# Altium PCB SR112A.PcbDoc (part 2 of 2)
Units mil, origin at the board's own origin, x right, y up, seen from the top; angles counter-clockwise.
Board outline 4000 x 3000 mil, 4 copper layers (Top Layer, Signal Layer 1, Signal Layer 2, Bottom Layer), stack 61.2 mil thick; 97 components, 25 nets, 179 pads, 677 vias.
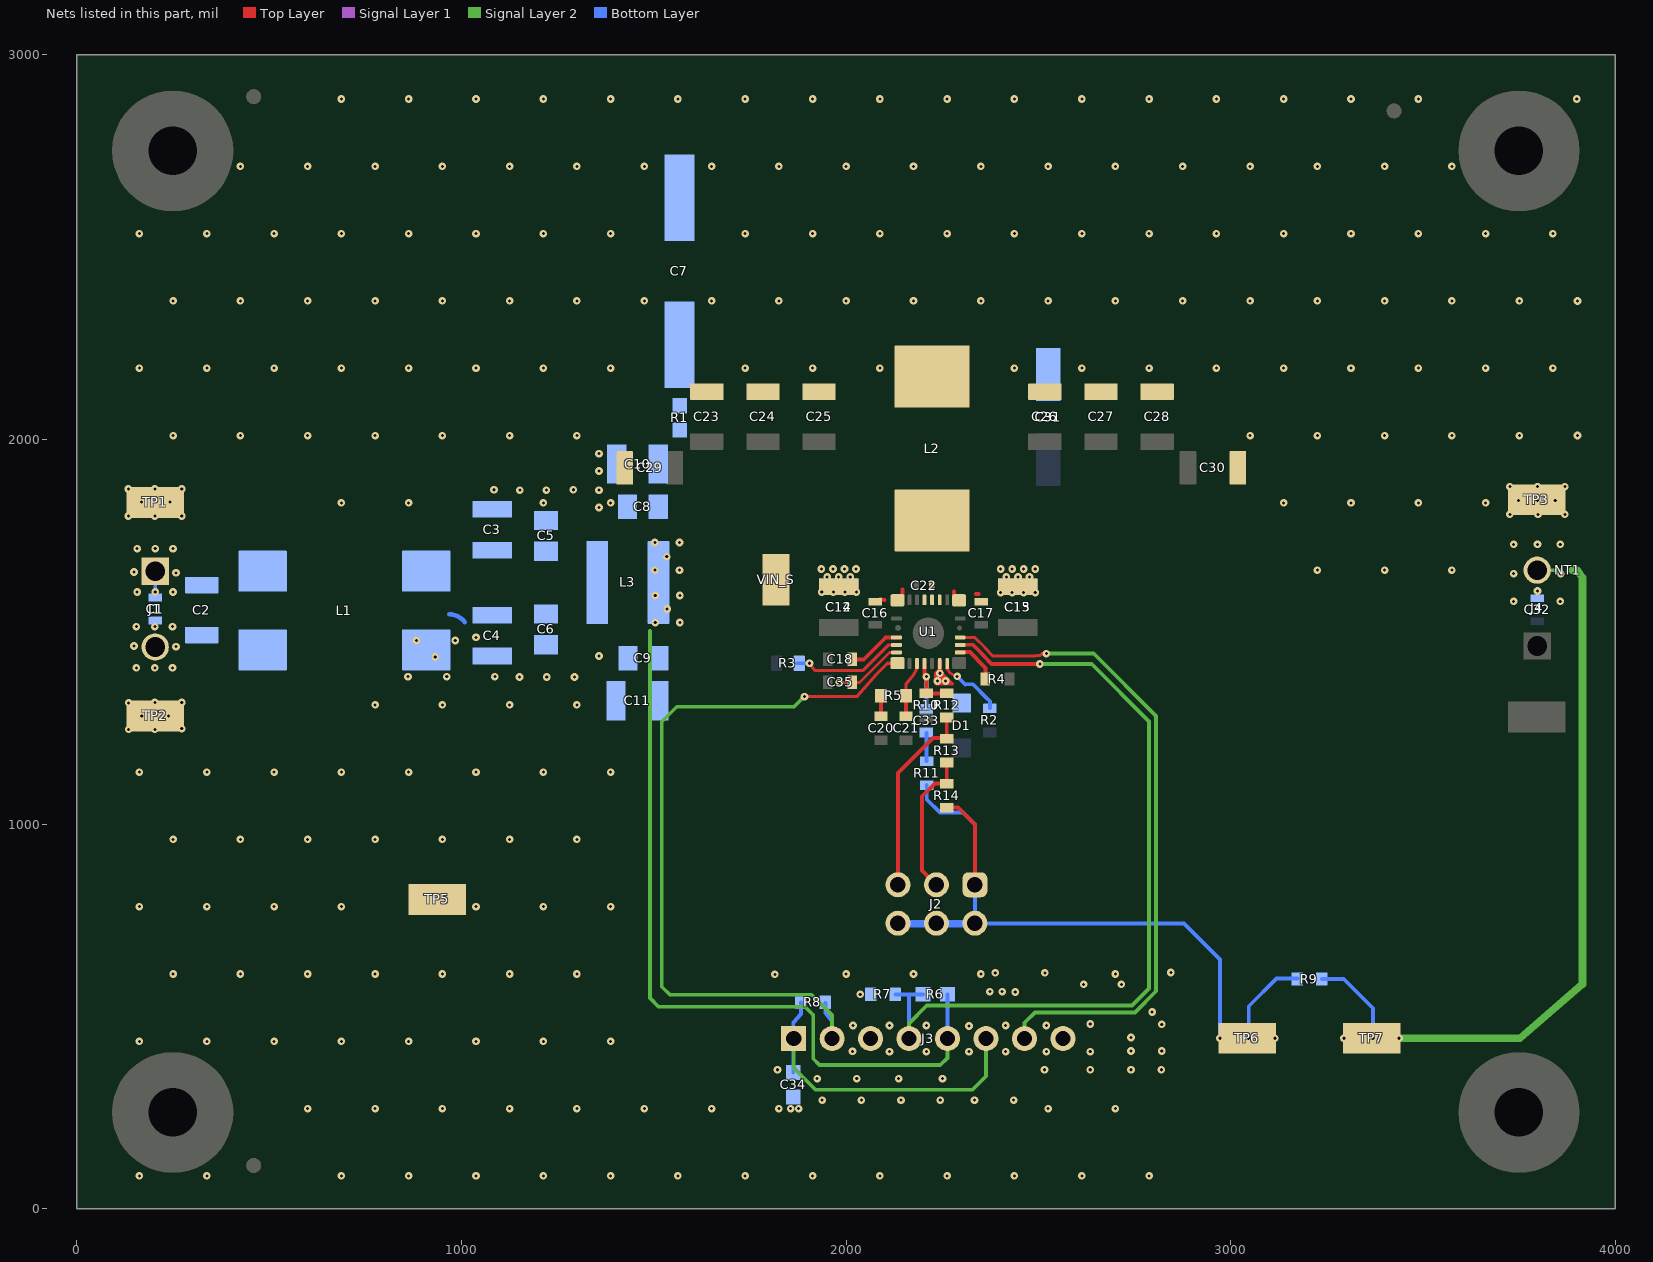
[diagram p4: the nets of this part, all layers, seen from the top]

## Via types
v1: diameter 20, hole 8, Top Layer to Bottom Layer, tented both sides, 441 vias
v2: diameter 19.68, hole 7.87, Top Layer to Bottom Layer, tented both sides, 208 vias
v3: diameter 20, hole 8, Top Layer to Bottom Layer, 28 vias

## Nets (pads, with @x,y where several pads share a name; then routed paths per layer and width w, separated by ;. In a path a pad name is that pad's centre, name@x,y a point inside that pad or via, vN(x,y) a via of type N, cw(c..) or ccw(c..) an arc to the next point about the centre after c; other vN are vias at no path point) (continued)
COMP: C21.2 R5.2 U1.3 | length 145.6
  Top Layer w8: R5.2@2156,1333 2156,1364 2177,1390 U1.3@2185,1405 ; U1.3@2183.38,1405.15 U1.3@2184.47,1417.26
  Top Layer w10: C21.2@2156,1281 R5.2@2156,1333
CONFIG: R2.2 U1.7 | length 180.3
  Top Layer w7: U1.7@2262,1404 2264.22,1400.51
  Top Layer w7.5: U1.7@2263,1417 2265,1401 ; 2265.06,1401.03 2270,1393
  Top Layer w8: 2270,1393 v1@2288,1383
  Bottom Layer w10: v1(2289,1384) 2310,1363 2329.81,1363.19 2365,1328 2374,1319 R2.2@2374,1301
DRSS: R3.2 U1.25 | length 309.8
  Top Layer w8: v1@1905,1413 v1(1905,1418) 1919,1399 ; 1919.31,1398.69 2043.15,1398.69 2109.46,1465 U1.25@2141,1465
  Bottom Layer w10: R3.2@1873,1418 v1(1905,1418)
EN: J3.4 R6.1 R7.2 U1.10 | length 2166.4
  Top Layer w10: U1.10@2288,1466 2330.23,1466 2343.19,1453.04 2378,1416 v1@2503.77,1416
  Signal Layer 2 w10: J3.4@2164,442 2164,481 2210,528 2743.81,528 2788.19,572.38 2788.19,1266.81 2639,1416 v1(2504,1416)
  Bottom Layer w10: R7.2@2128,557 2165,557 R6.1@2200.5,557 ; J3.4@2164,441 2164,556
FB: C33.1 R10.2 R12.2 U1.4 | length 225.1
  Top Layer w10: U1.4@2204,1426 2204,1391 v1(2209,1383) R10.2@2209,1339.5 R12.2@2262,1339.5 2262.5,1339.5 R12.2@2263,1340
  Bottom Layer w10: C33.1@2209,1300 v1(2209,1383)
GND: C3.2 C4.2 C5.2 C6.2 C7.2 C8.2 C9.2 C10.2 C11.2 C23.2 C24.2 C25.2 C26.2 C27.2 C28.2 C29.2 C30.2 C31.1 C32.1 C34.2 C35.1 D1.1 J3.3 J3.8 J4.2 L1.4 L2.2 NT1.1 R7.1 TP3.1 TP5.1 U1.6 U1.26 | length 452.8
  Top Layer w8: v1(1983.31,1368) C35.1@2016.5,1368 2035,1368 2113,1446 U1.26@2140,1446
  Top Layer w10: v1@2249.33,1392.33 2249.33,1390.4 2253.19,1386.55 2253.19,1386.04 2274.04,1365.18 2275.08,1365.18 2275.93,1364.81
  Top Layer w12: v1@2244,1366 v1@2244,1391.34 ; U1.6@2244,1425 2244,1400.34 2235,1391.34 2235,1366 v1@2256,1365.81 ; v1@2245.38,1399.06 v1@2247.91,1391.83 ; 2248,1366 v1@2248,1391.34 ; v1@2252,1366 2273,1365.81
  Signal Layer 2 w10: J4.2@3797,1659.85 3858.04,1659.85 NT1.1@3858.19,1660
  Bottom Layer w10: J4.2@3797,1632 J4.2@3797,1632.15
  other v1: 1856,260 1877,260 1938,282 2040,282 2143,282 2245,282 2334,282 2436,282 1925,338 2028,338 2137,338 2251,338 1822,361 2516,361 2635,361 2741,361 2820,361 2113,408 2209,408 2320,408 2415,408 2521,408 2635,408 2017,409 2741,410 2821,410 2741,445 2320,475 2018,476 2113,476 2209,476 2415,476 2521,476 2821,479 2635,480 2796,511 2037,557 2440,563 2374,564 2406,564 2618,583 2716,583 1815,609 2388,613 2517,613 2844.56,613.83 2238,1372 2259,1372 1151,1382 1222,1382 1294,1382 861,1383 962,1383 1087,1383 2244,1392 932,1434 1358,1437 883,1477 984,1477 3736,1579 3857,1579 3798,1606 3736,1651 3858,1651 3736,1727 3798,1727 3857,1727 3726,1805 3799,1805 3869,1805 1358,1823 3749,1841 3798,1841 3844,1841 1152,1868 1221,1868 1358,1868 1085,1869 1291,1869 3726,1877 3798,1877 3869,1877 1358,1918 1358,1963 3902,2010 3902,2360 3900,2885
  other v2: 163,85 338,85 688,85 863,85 1038,85 1213,85 1388,85 1563,85 1738,85 1913,85 2088,85 2263,85 2438,85 2613,85 2788,85 600.5,260 775.5,260 950.5,260 1125.5,260 1300.5,260 1475.5,260 1650.5,260 1825.5,260 2525.5,260 2700.5,260 163,435 338,435 513,435 688,435 863,435 1038,435 1213,435 1388,435 250.5,610 425.5,610 600.5,610 775.5,610 950.5,610 1125.5,610 1300.5,610 2000.5,610 2175.5,610 2350.5,610 2700.5,610 163,785 338,785 513,785 688,785 1038,785 1213,785 1388,785 250.5,960 425.5,960 600.5,960 775.5,960 950.5,960 1125.5,960 1300.5,960 163,1135 338,1135 513,1135 688,1135 863,1135 1038,1135 1213,1135 1388,1135 775.5,1310 950.5,1310 1125.5,1310 1300.5,1310 1038,1485 3225.5,1660 3400.5,1660 3575.5,1660 688,1835 863,1835 1213,1835 1388,1835 3138,1835 3313,1835 3488,1835 3663,1835 250.5,2010 425.5,2010 600.5,2010 775.5,2010 950.5,2010 1125.5,2010 1300.5,2010 3050.5,2010 3225.5,2010 3400.5,2010 3575.5,2010 3750.5,2010 163,2185 338,2185 513,2185 688,2185 863,2185 1038,2185 1213,2185 1388,2185 1738,2185 1913,2185 2088,2185 2438,2185 2613,2185 2788,2185 2963,2185 3138,2185 3313,2185 3488,2185 3663,2185 3838,2185 250.5,2360 425.5,2360 600.5,2360 775.5,2360 950.5,2360 1125.5,2360 1300.5,2360 1475.5,2360 1650.5,2360 1825.5,2360 2000.5,2360 2175.5,2360 2350.5,2360 2525.5,2360 2700.5,2360 2875.5,2360 3050.5,2360 3225.5,2360 3400.5,2360 3575.5,2360 3750.5,2360 163,2535 338,2535 513,2535 688,2535 863,2535 1038,2535 1213,2535 1388,2535 1738,2535 1913,2535 2088,2535 2263,2535 2438,2535 2613,2535 2788,2535 2963,2535 3138,2535 3313,2535 3488,2535 3663,2535 3838,2535 425.5,2710 600.5,2710 775.5,2710 950.5,2710 1125.5,2710 1300.5,2710 1475.5,2710 1650.5,2710 1825.5,2710 2000.5,2710 2175.5,2710 2350.5,2710 2525.5,2710 2700.5,2710 2875.5,2710 3050.5,2710 3225.5,2710 3400.5,2710 3575.5,2710 688,2885 863,2885 1038,2885 1213,2885 1388,2885 1563,2885 1738,2885 1913,2885 2088,2885 2263,2885 2438,2885 2613,2885 2788,2885 2963,2885 3138,2885 3313,2885 3488,2885
GND_SENSE: NT1.2 R9.2 TP7.1 | length 2083.5
  Signal Layer 2 w20: NT1.2@3888,1660 3901,1660 3915,1640 3915,583.74 3752.08,443 v1(3438,443) v1(3370,443) ; v1(3370,443) v1(3295,443) v1(3370,443)
  Bottom Layer w10: R9.2@3237,597 3294,597 3370,521 v1(3370,443)
INJ: J2.1 J2.2 J2.4 J2.6 R9.1 R11.2 R14.2 TP6.1 | length 2156.5
  Top Layer w10: R14.2@2262,1043 2291,1043 2335,999 J2.1@2335,842
  Signal Layer 1 w10: v1(2972,443) v1(3047,443) v1(3115,443)
  Bottom Layer w10: R11.2@2210,1101 2210,1064 2244,1030 2304,1030 2335,999 J2.1@2335,842 J2.2@2335,742 ; J2.2@2336,741 2879,741 2972,648 v1(2972,443) ; v1(3047,443) 3047,526 3119,598 R9.1@3174,598
  Bottom Layer w20: J2.6@2134,741 J2.4@2235,741 ; J2.4@2236,741 J2.2@2335,741
MODE/SYNC: J3.7 U1.11 | length 1742.1
  Top Layer w8: U1.11@2287,1485 2335,1485 2360,1460 2360,1459.7 2381.33,1437 2494.15,1437 2495.15,1438 2505,1438 2510,1443 v1(2521,1443)
  Signal Layer 2 w10: J3.7@2464,442 2464,483.19 2491,510.19 2751.19,510.19 2806,565 2806,1281 2644,1443 v1(2521,1443)
NetC3_1: C3.1 C4.1 C5.1 C6.1 L1.3 L3.2 | length 47
  Bottom Layer w12: 968.01,1545.33 cw(c967.04,1492.6) 1008.68,1524.97
NetC7_1: C7.1 R1.1
NetC20_1: C20.1 R5.1 | length 53
  Top Layer w10: C20.1@2091,1280 R5.1@2091,1333
NetC33_2: C33.2 R11.1 | length 73
  Bottom Layer w10: R11.1@2209,1164 C33.2@2209,1237
NetC34_1: C34.1 J3.1 J3.6 R8.1 | length 900.8
  Signal Layer 2 w10: J3.1@1864,442 1864,366 1921,309 2329,309 2364,344 J3.6@2364,442
  Bottom Layer w10: C34.1@1863,354 J3.1@1863,444 ; J3.1@1863,445 1863,484 1883,506 R8.1@1883,536
NetJ2_3: J2.3 R13.1 R14.1 | length 378
  Top Layer w10: J2.3@2235,842 2198,879 2198,1072 2231,1105 R14.1@2262,1105 R13.1@2262,1160
NetJ2_5: J2.5 R12.1 R13.2 | length 508.7
  Top Layer w10: J2.5@2135,842 2135,1133 2226,1224 2262,1224 R12.1@2262,1277
PG: J3.2 R8.2 U1.1 | length 1995.2
  Top Layer w8: v1(1892,1331) 2027.98,1331 2080,1390 2108,1418 U1.1@2134,1418
  Signal Layer 2 w10: v1(1892,1331) 1891,1331 1865,1305 1560,1305 1521,1266 1521,577 1542,556 1911,556 1931,536 1964,503 J3.2@1964,442
  Bottom Layer w10: 1946.91,507.93 1963,489 ; 1947,508 R8.2@1947,534.5 ; J3.2@1964,446 1964,488
RT: R4.2 U1.9 | length 118.6
  Top Layer w10: U1.9@2288,1446.8 2322.08,1446.8 2359,1409.88 ; 2360.41,1408.41 2362.5,1406.31 R4.2@2362.5,1377
SW: C22.2 L2.1 U1.16 U1.17 U1.18
VCC: C18.1 U1.24 | length 147.9
  Top Layer w10: C18.1@2016,1428 C18.1@2016.5,1428 2046.26,1428 2103.26,1485 ; 2103,1485 U1.24@2140,1485
VIN: C8.1 C9.1 C10.1 C11.1 C12.1 C13.1 C14.1 C15.1 C16.1 C17.1 J3.5 L3.1 R1.2 R6.2 U1.14 U1.21 VIN_S.1 | length 2121.7
  Top Layer w10: C16.1@2089,1585 2100,1582 ; U1.21@2133.78,1581.63 2147,1594.85 2147,1610 ; 2281,1605 2281,1594.85 U1.14@2294.22,1581.63 ; 2338,1598 2345,1598
  Signal Layer 2 w10: 1490,1502 1490,548 1512,525 1839,525 1893,525 1915,503 1915,389.5 1931.5,373 2245,373 2264,392 J3.5@2264,442
  Bottom Layer w10: J3.5@2263.5,441.5 R6.2@2263.5,557
  other v1: 1504,1524 1568,1524 1535,1559 1504,1594 1568,1594 2402,1602 2432,1602 2462,1602 2492,1602 1937,1603 1967,1603 1997,1603 2027,1603 1951,1642 1981,1642 2011,1642 2417,1642 2447,1642 2477,1642 1503,1660 1567,1660 1936,1663 1966,1663 1996,1663 2026,1663 2402,1663 2432,1663 2462,1663 2492,1663 1534,1695 1503,1732 1567,1732
VIN+: C1.1 C2.1 J1.1 L1.2 TP1.1 | length 55.4
  Top Layer w10: TP1.1@203,1836 TP1.1@204,1835
  Bottom Layer w10: v3(204,1603) J1.1@204,1656.85 J1.1@204,1657
  other v1: 203,1801 168,1837 242,1837 203,1871
  other v3: 157,1603 250,1603 258,1653 149,1655 157,1716 204,1716 250,1716 134,1801 273,1801 134,1871 273,1871
VIN-: C1.2 C2.2 J1.2 L1.1 TP2.1
  other v3: 135,1246 203,1246 273,1248 169,1281 238,1281 135,1315 203,1316 273,1316 155,1406 203,1406 249,1406 258,1461 149,1463 155,1513 203,1513 249,1513
pads on no net: FID1.1 FID2.1 FID3.1 FID4.1 FID5.1 FID6.1 H1.1 H2.1 H3.1 H4.1 H5.0 H6.0 H7.0 H8.0 LBL1.0 SH-J1.0 SH-J2.0 SH-J3.0 U1.2 U1.5 U1.15 U1.20

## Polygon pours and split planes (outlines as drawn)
GND_SENSE on Top Layer "TOP_LAYER_GND_SENSE_P2690" (solid, remove dead copper, pour order 2690): 3279.64,495 3453.65,495 3453.65,391 3279.64,391
INJ on Top Layer "TOP_LAYER_INJ_P2691" (solid, remove dead copper, pour order 2691): 2955.64,494.76 3129.64,494.76 3129.64,390.76 2955.64,390.76
VIN on Top Layer "TOP_LAYER_VIN_P2692" (solid, remove dead copper, pour order 2692): 2276,1566 2527,1566 2527,1706 2344,1706 2276,1636
VIN on Top Layer "TOP_LAYER_VIN_P2693" (solid, remove dead copper, pour order 2693): 2152,1566 1781,1566 1781,1706 2103.61,1706 2152,1657.61
GND on Top Layer "TOP_LAYER_GND_P2694" (solid, remove dead copper, pour order 2694): 3709,1899.53 3709,1558 3884,1558 3884,1900.51
VIN- on Top Layer "TOP_LAYER_VIN-_P2695" (solid, remove dead copper, pour order 2695): 109,1222 109,1545 299,1545 299,1222
VIN+ on Top Layer "TOP_LAYER_VIN+_P2696" (solid, remove dead copper, pour order 2696): 109,1896 109,1571 299,1571 299,1896
GND on Top Layer "TOP_LAYER_GND_P2697" (solid, remove dead copper, pour order 2697): 849.77,1360.44 606.77,1360.44 394.19,1154 849.77,1154
GND on Top Layer "TOP_LAYER_GND_P2698" (solid, remove dead copper, pour order 2698): 1485.15,2066.88 1485.15,1552.88 24.15,1552.88 24.15,2066.88
GND on Top Layer "TOP_LAYER_GND_P2699" (solid, remove dead copper, pour order 2699): 1779,2975 1779,2064 25,2064 25,2975
GND on Top Layer "TOP_LAYER_GND_P2700" (solid, remove dead copper, pour order 2700): 1485,1159 1485,634.39 2003.85,634.39 2858,634.39 2858,25 33.24,25 26,32.24 26,1159
GND on Top Layer "TOP_LAYER_GND_P2701" (solid, remove dead copper, pour order 2701): 1773,2975 1773,2064 2951,2064 2951,1920 3324,1547 3975,1547 3975,2975
-VOUT on Top Layer "TOP_LAYER_-VOUT_P2702" (solid, remove dead copper, pour order 2702): 1495,2054 2949,2054 2949,1908 3320,1537 3975,1537 3975,25 2869,25 2869,640 2870,641 1495,641
GND on Signal Layer 2 "SIGNAL_LAYER_2_GND_P2720" (solid, remove dead copper, pour order 2720): 25,2975 26,2974 26,25 3975,25 3975,2975
INJ on Signal Layer 2 "SIGNAL_LAYER_2_INJ_P2713" (solid, remove dead copper, pour order 2713): 2955.98,494.96 3129.98,494.96 3129.98,390.96 2955.98,390.96
GND_SENSE on Signal Layer 2 "SIGNAL_LAYER_2_GND_SENSE_P2712" (solid, remove dead copper, pour order 2712): 3280,495 3454,495 3454,391 3280,391
GND on Signal Layer 2 "SIGNAL_LAYER_2_GND_P2714" (solid, remove dead copper, pour order 2714): 850,1361 607,1361 351.63,1113 850,1113
VIN on Signal Layer 2 "SIGNAL_LAYER_2_VIN_P2715" (solid, remove dead copper, pour order 2715): 1485.26,1770.9 1485.36,1771 1805,1770.9 2526,1770.9 2526,1589 1901,1589 1805,1493 1485,1493 1485,1771
GND on Signal Layer 2 "SIGNAL_LAYER_2_GND_P2716" (solid, remove dead copper, pour order 2716): 1836.42,2067 1448.03,1553 24,1553 24,2067
GND on Signal Layer 2 "SIGNAL_LAYER_2_GND_P2717" (solid, remove dead copper, pour order 2717): 1778.5,2974 1778.5,2047.79 25.5,2047.79 25.5,2974
GND on Signal Layer 2 "SIGNAL_LAYER_2_GND_P2718" (solid, remove dead copper, pour order 2718): 3975,2974 3975,1553 3098.51,1553 2228.68,2430.92 2228.68,2974
GND on Signal Layer 2 "SIGNAL_LAYER_2_GND_P2719" (solid, remove dead copper, pour order 2719): 1466,1149 1466,631 2004,631 2856,631 2856,27 28,27 27,28 27,1149
INJ on Bottom Layer "BOTTOM_LAYER_INJ_P2726" (solid, remove dead copper, pour order 2726): 2955.64,494.76 3129.64,494.76 3129.64,390.76 2955.64,390.76
GND_SENSE on Bottom Layer "BOTTOM_LAYER_GND_SENSE_P2725" (solid, remove dead copper, pour order 2725): 3280,495 3454,495 3454,391 3280,391
GND on Bottom Layer "BOTTOM_LAYER_GND_P2722" (solid, remove dead copper, pour order 2722): 2226,1402 2226,1362.91 2260.5,1288 2326,1288 2326,1338 2262,1402
GND on Bottom Layer "BOTTOM_LAYER_GND_P2736" (solid, remove dead copper, pour order 2736): 1730,2975 1730,2063.93 2951,2063.93 2951,1919 3323,1547 3975,1547 3975,2975
-VOUT on Bottom Layer "BOTTOM_LAYER_-VOUT_P2737" (solid, remove dead copper, pour order 2737): 1469.04,2054 2949,2054 2949,1907 3319,1537 3975,1537 3975,25 3966.67,25 2843.04,25 2843.04,644 1469.04,644
GND on Bottom Layer "BOTTOM_LAYER_GND_P2721" (solid, remove dead copper, pour order 2721): 3779,1584 3815,1584 3815,1685 3779,1685
VIN on Bottom Layer "BOTTOM_LAYER_VIN_P2723" (solid, remove dead copper, pour order 2723): 1925,1592 1925,1674 2039,1674 2039,1592
VIN on Bottom Layer "BOTTOM_LAYER_VIN_P2724" (solid, remove dead copper, pour order 2724): 2389,1591 2389,1675 2504,1675 2504,1591
NetC7_1 on Bottom Layer "BOTTOM_LAYER_NETC7_1_P2727" (solid, remove dead copper, pour order 2727): 1527,2360 1527,2066 1609,2066 1609,2360
GND on Bottom Layer "BOTTOM_LAYER_GND_P2728" (solid, remove dead copper, pour order 2728): 850,1360 607,1360 389.73,1149 850,1149
NetC3_1 on Bottom Layer "BOTTOM_LAYER_NETC3_1_P2729" (solid, remove dead copper, pour order 2729): 837,1736 1381,1736 1381,1519 837,1519
VIN- on Bottom Layer "BOTTOM_LAYER_VIN-_P2730" (solid, remove dead copper, pour order 2730): 103,1545 553,1545 553,1386.28 375.3,1218 103,1218
VIN+ on Bottom Layer "BOTTOM_LAYER_VIN+_P2731" (solid, remove dead copper, pour order 2731): 103,1565 103,1900 376,1900 553,1723 553,1565
VIN on Bottom Layer "BOTTOM_LAYER_VIN_P2732" (solid, remove dead copper, pour order 2732): 1483,1169 1483,2048 1650,2048 1650,1169
GND on Bottom Layer "BOTTOM_LAYER_GND_P2733" (solid, remove dead copper, pour order 2733): 1652.41,2072 1446.74,1551.9 22.71,1551.9 22.71,2072
GND on Bottom Layer "BOTTOM_LAYER_GND_P2734" (solid, remove dead copper, pour order 2734): 1778.99,2975 1778.99,2065 25,2065 25,2975
GND on Bottom Layer "BOTTOM_LAYER_GND_P2735" (solid, remove dead copper, pour order 2735): 1463,1152 1463,634 2006,634 2858,634 2858,25 35,25 26,34 26,1152 1449,1152
INJ on Signal Layer 1 "SIGNAL_LAYER_1_INJ_P2705" (solid, remove dead copper, pour order 2705): 2955.98,494.96 3129.98,494.96 3129.98,390.96 2955.98,390.96
GND_SENSE on Signal Layer 1 "SIGNAL_LAYER_1_GND_SENSE_P2704" (solid, remove dead copper, pour order 2704): 3280,495 3454,495 3454,391 3280,391
GND on Signal Layer 1 "SIGNAL_LAYER_1_GND_P2710" (solid, remove dead copper, pour order 2710): 1726,2975 1726,2063.56 2950.95,2063.56 2950.95,1920.05 3324,1547 3975,1547 3975,2975
-VOUT on Signal Layer 1 "SIGNAL_LAYER_1_-VOUT_P2711" (solid, remove dead copper, pour order 2711): 1495,2054 2949,2054 2949,1908 3320,1537 3975,1537 3975,25 2869,25 2869,640 2870,641 1495,641
GND on Signal Layer 1 "SIGNAL_LAYER_1_GND_P2706" (solid, remove dead copper, pour order 2706): 849.08,1361.13 606.08,1361.13 374.26,1136 849.08,1136
GND on Signal Layer 1 "SIGNAL_LAYER_1_GND_P2707" (solid, remove dead copper, pour order 2707): 1485,2067 1485,1553 24,1553 24,2067
GND on Signal Layer 1 "SIGNAL_LAYER_1_GND_P2708" (solid, remove dead copper, pour order 2708): 1778.5,2975 1778.5,2064 25.5,2064 25.5,2975
GND on Signal Layer 1 "SIGNAL_LAYER_1_GND_P2709" (solid, remove dead copper, pour order 2709): 1485,1155.96 1485.5,631.35 2006.25,631.35 2858.25,631.35 2858.25,25 32.6,25 26,31.6 26,1155.96

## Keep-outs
Keep-Out Layer:
  text ".Layer_Name" at 577,-858.49 h60

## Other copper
Top Layer:
  rectangle net GND: 1379,1366 1485,1486
  rectangle net GND: 842.26,1147 1485,1385
  rectangle net GND: 840,1370 1381,1556
  region net GND: 3884,1900 3707,1900 3707,1791 3884,1791
  pour cut-out: 2160,1563 2160,1549 2268,1549 2268,1563
  pour cut-out: 100,1958 100,1906 309.5,1906 309.5,1958
  pour cut-out: 608.04,1359.71 402.04,1159.71 402.04,1209.81 560.05,1359.71
  pour cut-out: 403.26,1957.39 403.26,1907.84 561.26,1749.84 609.66,1749.84
  pour cut-out: 2075,2063.72 2075,1871 2373,1871 2373,2063.72
  pour cut-out: 2075,1871 2075,1716 2124,1716 2124,1871
  pour cut-out: 2159,1437 2159,1431 2265,1431 2265,1437
  pour cut-out: 1381,1767 1381,1489 1485,1489 1485,1767
  pour cut-out: 553,1750 553,1360 839,1360 839,1750
  pour cut-out: 99.5,1211 99.5,1159 309,1159 309,1211
  pour cut-out: 309.5,1958 309.5,1159 584,1159 584,1958
  pour cut-out: 26,1958 26,1159 100,1159 100,1958
  region net SW: 2198,1569 2250,1569 2250,1635 2324,1709 2324,1871 2124,1871 2124,1709 2198,1635
  pour cut-out: 2323,1871 2323,1713 2373,1713 2373,1871
  text ".Layer_Name" at 577,-858.49 h60
Signal Layer 1:
  rectangle net GND: 841.57,1150 1485,1433
  rectangle net GND: 1374,1370 1485,1490
  rectangle net GND: 840,1371 1381,1557
  pour cut-out: 608.43,1359.71 402.43,1159.71 402.43,1209.81 560.44,1359.71
  pour cut-out: 402.96,1957.55 402.96,1908 560.96,1750 609.36,1750
  pour cut-out: 1381,1767 1381,1489 1485,1489 1485,1767
  pour cut-out: 26,1958 26,1159 583,1159 583,1958
  pour cut-out: 553,1750 553,1360 839,1360 839,1750
Signal Layer 2:
  rectangle net GND: 1374,1117 1465,1490
  rectangle net GND: 842.94,1143 1381,1498.23
  rectangle net GND: 839,1370 1381,1556
  pour cut-out: 607.66,1359.71 401.66,1159.71 401.66,1209.81 559.67,1359.71
  pour cut-out: 402.96,1957.55 402.96,1908 560.96,1750 609.36,1750
  pour cut-out: 553,1750 553,1360 839,1360 839,1750
  pour cut-out: 1381,1767 1381,1489 1485,1489 1485,1767
  pour cut-out: 26,1958 26,1159 584,1159 584,1958
Bottom Layer:
  rectangle net GND: 1365,1138 1463,1489
  rectangle net GND: 843.35,1145 1380,1498
  rectangle net NetC3_1: 845,1607 971,1715
  rectangle net VIN+: 421,1608 546,1714
  pour cut-out: 609,1360 403,1160 403,1210.1 561.01,1360
  pour cut-out: 403,1957.55 403,1908 561,1750 609.4,1750
  pour cut-out: 99.25,1212 99.25,1159 402,1159 402,1212
  pour cut-out: 100.03,1958.21 100.03,1905.21 403,1905.21 403,1958.21
  pour cut-out: 25.93,1958.06 25.93,1157.06 99.93,1157.06 99.93,1958.06
  pour cut-out: 1381,1767 1381,1489 1485,1489 1485,1767
  pour cut-out: 553,1750 553,1360 839,1360 839,1750
  pour cut-out: 844,1539.5 844,1509 1002,1509 1002,1539.5
  pour cut-out: 78,1587 78,1531 84.5,1531 84.5,1587
  text ".Layer_Name" at 577,-858.49 h60

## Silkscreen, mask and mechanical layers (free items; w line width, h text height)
Top Overlay:
  text "LM67680-Q1 IBB Converter EVM" at 1009,2839 h150
  text "SR112A" at 516.06,2765.68 h72.83
  text "VIN [3.8V to (65V-|VOUT|)]" at 34.3,2026.88 h100
  text "GND" at 3743,1928 h40
  text "VIN+" at 144.69,1923.68 h72.83
  text "-VOUT" at 3703,1153 h40
  text "VIN-" at 147.97,1138.68 h72.83
  text "VOUT -3.3V to -12V" at 3148.31,1053.99 h100
  text "IOUT up to 6A" at 3220.15,952.32 h100
  text "-VOUT" at 2403,780 h40
  text "Select" at 2404,721 h40
  text "GND" at 882,682 h45
  text "-3.3V" at 2052,656 h25
  text "-12V" at 2293,656 h25
  text "-5V" at 2197,655 h25
  text "GND_SENSE" at 3183,327 h45
  text "INJ" at 2990,323 h45
  text "PG" at 1943,290 h45 r45
  text "EN" at 2144,289 h45 r45
  text "VIN" at 2217,263 h45 r45
  text "GND" at 2513,258 h45 r45
  text "GND" at 2012,257 h45 r45
  text "EXT_PU" at 1715,162 h45 r45
  text "EXT_PU" at 2217,162 h45 r45
  text "MODE/SYNC" at 2224,66 h45 r45
  text ".Layer_Name" at 577,-858.49 h60
Bottom Overlay:
  text ".Layer_Name" at 577,-858.49 h60
Top Paste:
  text ".Layer_Name" at 577,-858.49 h60
Bottom Paste:
  text ".Layer_Name" at 577,-858.49 h60
Top Solder:
  rectangle: 123,1234 285,1328
  rectangle: 122,1789 286,1883
  text ".Layer_Name" at 577,-858.49 h60
  text ".Layer_Name" at 577,-858.49 h60
Bottom Solder:
  text ".Layer_Name" at 577,-858.49 h60
Drill Guide:
  text ".Layer_Name" at 577,-858.49 h60
M1 Board Outline:
  the board outline again, w10
  text ".Layer_Name" at 577,-858.49 h60
M2 Board Dimensions:
  rectangle: 125,-400 500,-275
  rectangle: 0,-275 125,-150
  lines w7: 0,-275 1000,-275 ; 125,-400 125,-150 ; 250,-400 250,-150 ; 500,-400 500,-150 ; 750,-400 750,-150 ; 0,-400 0,-150 1000,-150 1000,-400 0,-400
  text ".Layer_Name" at 577,-858.49 h60
M3 3D STEP Top:
  text ".Layer_Name" at 577,-858.49 h60
M4 3D STEP Bottom:
  text ".Layer_Name" at 577,-858.49 h60
M5 Assembly Top:
  lines w10: -292,-930.17 6308,-930.17 ; -292,-726.83 6310,-726.83 ; -292,-523.5 -292,-1133.5 3713,-1133.5 6310,-1133.5 6310,-523.5 -291.5,-523.5 -291.5,-1133.5 1284,-1133.5 ; 2173,-1133.5 2173,-523.5 ; 3440,-726.83 3440,-523.5 ; 4280,-726.83 4280,-523.5 ; 4902,-1140 4902,-937.17
  text "COMPONENTS MARKED 'DNP' SHOULD NOT BE POPULATED." at 1153.5,-318.5 h60
  text "ASSEMBLY VARIANT:" at 1153,-434 h60
  text ".VariantName" at 2189,-434 h60
  text "PCB VIEWED FROM TOP SIDE" at -228.5,-655.67 h60
  text "BOARD #:" at 2248,-655.67 h60
  text ".PRJ_Number" at 2793.5,-655.67 h60
  text "REV:" at 3638,-655.67 h60
  text ".PCB_Rev" at 3929.5,-655.67 h60
  text "SVN REV:" at 4476,-655.67 h60
  text ".VersionControl_RevNumber" at 4982,-655.67 h60
  text "TID #:" at 2248,-859 h60
  text ".TID" at 2793.5,-859 h60
  text "PLOT NAME =" at -228.5,-1064.34 h60
  text ".plot_File_Name" at 577,-1064.34 h60
  text "GENERATED    :" at 2250,-1064.34 h60
  text ".Print_Date" at 3119.5,-1064.34 h60
  text ".Print_Time" at 3848.5,-1064.34 h60
  text "TEXAS INSTRUMENTS" at 5113,-1064.34 h60
M6 Assembly Bottom:
  lines w10: -292.5,-727.33 6309.5,-727.33 ; -290.5,-930.67 6309.5,-930.67 ; 1115.5,-1140.5 1115.5,-937.67 ; 1737.5,-727.33 1737.5,-524 ; 2577.5,-727.33 2577.5,-524 ; 3844.5,-1134 3844.5,-524 ; 4733.5,-1134 6309,-1134 6309,-524 -292.5,-524 -292.5,-1134 2304.5,-1134 6309.5,-1134 6309.5,-524
  text "COMPONENTS MARKED 'DNP' SHOULD NOT BE POPULATED." at 6102,-318 h60
  text ".VariantName" at 5058,-434 h60
  text "ASSEMBLY VARIANT:" at 6097,-434 h60
  text ".VersionControl_RevNumber" at 1035.5,-656.17 h60
  text "SVN REV:" at 1541.5,-656.17 h60
  text ".PCB_Rev" at 2088,-656.17 h60
  text "REV:" at 2379.5,-656.17 h60
  text ".PRJ_Number" at 3224,-656.17 h60
  text "BOARD #:" at 3769.5,-656.17 h60
  text "PCB VIEWED FROM BOTTOM SIDE" at 6246,-656.17 h60
  text ".TID" at 3224,-859.5 h60
  text "TID #:" at 3769.5,-859.5 h60
  text "TEXAS INSTRUMENTS" at 904.5,-1064.84 h60
  text ".Print_Time" at 2169,-1064.84 h60
  text ".Print_Date" at 2898,-1064.84 h60
  text "GENERATED    :" at 3767.5,-1064.84 h60
  text ".plot_File_Name" at 5440.5,-1064.84 h60
  text "PLOT NAME =" at 6246,-1064.84 h60
M9 Title Sheet:
  drawing of 57 lines, arcs and shapes, not listed
  text "1" at 739.84,8036.5 h70
  text "2" at 3235.5,8036.5 h70
  text "3" at 5724.84,8036.5 h70
  text "4" at 8231.51,8036.5 h70
  text "5" at 10730.5,8036.5 h70
  text "6" at 13235.5,8036.5 h70
  text "A" at -416.5,6893.5 h70
  text "B" at -416.5,4513.5 h70
  text "B" at 14383.5,4513.5 h70
  text "C" at -416.5,2138.5 h70
  text "C" at 14383.5,2138.5 h70
  text "PROJECT TITLE:" at 11343.5,277.5 h45
  text ".PRJ_Title" at 11393.5,144.17 h70
  text "DESIGNED FOR:" at 11343.5,-23.5 h45
  text ".PRJ_Customer" at 11393.5,-163.5 h70
  text "D" at -416.5,-231.5 h70
  text "D" at 14383.5,-231.5 h70
  text "FILE NAME:" at 11343.5,-323.5 h45
  text ".PCB_File_Name_No_Path" at 11393.5,-443.5 h70
  text "Texas Instruments (TI) and/or its licensors do not warrant the accuracy or completeness of this specification" at 6374,-605.34 h45
  text "ENGINEER:" at 11343.5,-613.5 h45
  text "LAYOUT BY:" at 12848.5,-613.5 h45
  text "or any information contained therein. TI and/or its licensors do not warrant that this design will meet" at 6329.01,-718 h45
  text ".PRJ_Engineer" at 11393.5,-768.49 h70
  text ".PCB_Layout" at 12899,-768.49 h70
  text "the specifications, will be suitable for your application or fit for any particular purpose, or will operate in" at 6329.01,-830.67 h45
  text ".Layer_Name" at 577,-858.49 h60
  text "ALTIUM DESIGNER VERSION:" at 12848.5,-923.5 h45
  text "an implementation. TI and/or its licensors do not warrant that the design is production worthy. You should" at 6329.01,-943.33 h45
  text "completely validate and test your design implementation to confirm the system functionality for your application." at 6374,-1056 h45
  text ".print_Scale" at 11393.5,-1056.83 h70
  text ".Application_BuildNumber" at 12899,-1056.83 h70
  text "1" at 739.84,-1263.5 h70
  text "2" at 3235.5,-1263.5 h70
  text "3" at 5724.84,-1263.5 h70
  text "4" at 8231.51,-1263.5 h70
  text "5" at 10730.5,-1263.5 h70
  text "6" at 13235.5,-1263.5 h70
M10 Fab Notes:
  drawing of 189 lines, arcs and shapes, not listed
  text "DESIGN INFORMATION" at 12382.02,6356.17 h60
  text "MIN. TRACK WIDTH:" at 11737.46,6224.05 h60
  text "8" at 12833.7,6224.05 h60
  text "MIL" at 12988.46,6224.05 h60
  text "MIN. CLEARANCE:" at 11737.46,6099.92 h60
  text "0.2" at 12773.7,6099.93 h60
  text "mm" at 12988.46,6099.92 h60
  text "MIN. VIA PAD SIZE:" at 11737.46,5975.8 h60
  text "20" at 12803.71,5975.8 h60
  text "MIL" at 12988.46,5975.8 h60
  text "0.05mm (2MIL)" at 12432.46,5845.9 h60
  text "MINIMUM ANNULAR RING" at 11408.23,5837.67 h60
  text "EXTERNAL" at 13140.46,5837.67 h60
  text "PER" at 11608.23,5727.55 h60
  text "IPC-D-275 CLASS 2 LEVEL C" at 11828.23,5727.54 h60
  text "MIL, HOLES" at 13316.46,5627.07 h60
  text "+/-" at 12924,5618.48 h60
  text "+/-" at 13778,5618.48 h60
  text "REGISTRATION TOLERANCES:" at 11408.23,5617.42 h60
  text "METAL" at 12608,5617.42 h60
  text "5" at 13184.2,5617.42 h60
  text "3" at 14017.2,5617.42 h60
  text "MIL" at 14133.46,5617.42 h60
  text "HOLE SIZE TOLERANCE (UNLESS OTHERWISE SPECIFIED):" at 11408.23,5519.1 h60
  text "+/-" at 13778,5516.23 h60
  text "3" at 14017.2,5515.17 h60
  text "MIL" at 14133.46,5515.17 h60
  text "MATERIAL:" at 11333.46,5377.52 h60
  text "FR-4 High Tg" at 12319.9,5249 h60
  text "X" at 12175.46,5241.01 h60
  text "FR-408" at 11754.46,5236.49 h60
  text "OTHER" at 13242.46,5236.49 h60
  text "62 MIL (1.6mm) +/-10%" at 12074.56,5093.46 h60
  text "X" at 11954.46,5091.01 h60
  text "THICKNESS:" at 11408.23,5085.24 h60
  text "OTHER" at 13359.46,5085.24 h60
  text "TOLERANCE:" at 11408.23,4946.92 h60
  text "X" at 12256.46,4946.92 h60
  text "ANSI IPC-6012 TYPE 3 CLASS 2" at 12434.48,4946.92 h60
  text "OTHER +/-" at 12434.46,4802.73 h60
  text "BOW & TWIST:" at 11408.23,4657.54 h60
  text "X" at 12256.46,4657.54 h60
  text "ANSI IPC-6012 TYPE 3 CLASS 2" at 12434.48,4657.54 h60
  text "OTHER +/-" at 12434.46,4510.85 h60
  text "DRILLING:" at 11333.46,4380.23 h60
  text "NC_DRILL FILES" at 13094.46,4275.04 h60
  text "REFERENCE:" at 11408.23,4271.1 h60
  text "X" at 12065.46,4271.01 h60
  text "AS SHOWN" at 12243.46,4271.1 h60
  text "X" at 12966.46,4271.1 h60
  text "OTHER" at 13392.46,4128.85 h60
  text "PTH COPPER THICKNESS:" at 11407.91,4125.32 h60
  text "X" at 12547.14,4125.32 h60
  text "20-30 um" at 12675.14,4125.32 h60
  text "BOARD FINISH:" at 11333.46,3977.73 h60
  text "SILKSCREEN:" at 11488.68,3867.6 h60
  text "X" at 12446.46,3867.6 h60
  text "TOP" at 12563.46,3867.6 h60
  text "X" at 12956.46,3867.6 h60
  text "BOTTOM" at 13074.46,3867.6 h60
  text "SILKSCREEN COLOR:" at 11488.68,3712.41 h60
  text "X" at 12445.46,3712.41 h60
  text "WHITE" at 12563.46,3712.41 h60
  text "OTHER" at 13074.46,3712.41 h60
  text "X" at 12576.46,3568.96 h60
  text "GREEN" at 12694.46,3568.96 h60
  text "OTHER" at 13312.46,3568.96 h60
  text "SOLDER RESIST COLOR:" at 11488.68,3562.1 h60
  text "X" at 12576.46,3414.71 h60
  text "MATTE" at 12694.46,3414.71 h60
  text "SEMI-GLOSS" at 13312,3414.07 h60
  text "IMMERSION GOLD (ENIG)" at 12394.46,3241.94 h60
  text "ENEPIG" at 13732,3234.72 h60
  text "SURFACE FINISH:" at 11333.46,3233.72 h60
  text "X" at 12216.46,3233.72 h60
  text "IMM. TIN/SILVER OR EQUIV" at 11663,3096.4 h60
  text "OTHER" at 13094.46,3092.47 h60
  text "ARRAY/PANEL:" at 11333.46,2937.09 h60
  text "CUT AND TRIM PER M1 BOARD OUTLINE" at 12394.46,2928.87 h60
  text "N.C. ROUTE" at 12394.46,2792.9 h60
  text "X" at 13082.46,2792.9 h60
  text "V. SCORE" at 13260.46,2792.9 h60
  text "CERTIFICATION:" at 11333.46,2663.77 h60
  text "MATERIALS AND WORKMANSHIP FOR ALL PCBS" at 12058.46,2663.77 h60
  text "TO MEET OR EXCEED THE REQUIREMENTS OF:" at 12058.46,2569.71 h60
  text "X" at 11695.97,2441.08 h60
  text "ANSI IPC-A-600F CLASS ->" at 11823.96,2441.08 h60
  text "X" at 13471.97,2441.08 h60
  text "2" at 13581.96,2441.08 h60
  text "1" at 13266.96,2439.58 h60
  text "3" at 13935.96,2439.58 h60
  text "X" at 12507.97,2293.39 h60
  text "RoHS" at 12635.96,2293.39 h60
  text "OTHER" at 13280.36,2293.39 h60
  text "PER ORDER" at 13677.42,2293.39 h60
  text "ALL BOARDS MUST MEET OR EXCEED UL94-V0 REQUIREMENTS." at 11361,2139.57 h60
  text "PCB MUST BEAR THE UL94V-0 UL REGISTERED MATERIAL ID NUMBER" at 11361,2023.5 h60
  text "ADDITIONAL REQUIREMENTS:" at 11333.46,1854.08 h60
  text "MICROSECTION:" at 11408.23,1746.95 h60
  text "YES" at 12313.96,1746.95 h60
  text "REQUIRED" at 13175.46,1602.62 h60
  text "BARE BOARD ELEC. TEST:" at 11408.23,1599.76 h60
  text "NONE" at 12713.96,1599.76 h60
  text "X" at 13057.46,1599.76 h60
  text "PER ORDER" at 13767.46,1599.76 h60
  text "XX MIL VIAS REQUIRE NON-CONDUCTIVE FILL AND PLANARIZE" at 11576.38,1394.82 h59
  text "XX MIL VIAS REQUIRE CONDUCTIVE FILL AND PLANARIZE" at 11584.38,1290.84 h60
  text "OUTER XX MIL TRACES REQUIRE 50 OHM SINGLE-ENDED IMPEDANCE" at 11583.39,1127.46 h58
  text "LAYER 2 & 3 (INNER LAYERS) XX MIL WIDE, XX MIL SPACE / TRACES REQUIRE 100 OHM DIFFERENTIAL IMPEDANCE" at 11575.39,891.74 h60
  text ".Layer_Name" at 577,-858.49 h60
M11 Gerber Information:
  lines w10: -292,-930.17 6308,-930.17 ; -292,-726.83 6310,-726.83 ; -292,-523.5 -292,-1133.5 3713,-1133.5 6310,-1133.5 6310,-523.5 -291.5,-523.5 -291.5,-1133.5 1284,-1133.5 ; 2173,-1133.5 2173,-523.5 ; 3440,-726.83 3440,-523.5 ; 4280,-726.83 4280,-523.5 ; 4902,-1140 4902,-937.17
  text "ALL ARTWORK VIEWED FROM TOP SIDE" at -228.5,-655.67 h60
  text "BOARD #:" at 2248,-655.67 h60
  text ".PRJ_Number" at 2793.5,-655.67 h60
  text "REV:" at 3638,-655.67 h60
  text ".PCB_Rev" at 3929.5,-655.67 h60
  text "SVN REV:" at 4476,-655.67 h60
  text ".VersionControl_RevNumber" at 4982,-655.67 h60
  text "LAYER NAME =" at -228.5,-858.49 h60
  text "TID #:" at 2248,-859 h60
  text ".TID" at 2793.5,-859 h60
  text "PLOT NAME =" at -228.5,-1064.34 h60
  text ".plot_File_Name" at 577,-1064.34 h60
  text "GENERATED    :" at 2250,-1064.34 h60
  text ".Print_Date" at 3119.5,-1064.34 h60
  text ".Print_Time" at 3848.5,-1064.34 h60
  text "TEXAS INSTRUMENTS" at 5113,-1064.34 h60
M12 Stackup:
  drawing of 527 lines, arcs and shapes, not listed
  text "Layer" at 5468.74,7652 h60
  text "Name" at 5878.66,7652 h60
  text "Material" at 6818.4,7652 h60
  text "Thickness" at 7678.16,7652 h60
  text "Constant" at 8328,7652 h60
  text "Board Layer Stack" at 8897.86,7652 h60
  text "Board Layer Stack" at 10017.54,7652 h60
  text "Top Overlay" at 5878.66,7532 h60
  text "Top Solder" at 5878.66,7412 h60
  text "Solder Resist" at 6818.4,7412 h60
  text "0.40mil" at 7678.16,7412 h60
  text "3.5" at 8328,7412 h60
  text "1" at 5468.74,7292 h60
  text "Top Layer" at 5878.66,7292 h60
  text "2.80mil" at 7678.16,7292 h60
  text "Dielectric1" at 5878.66,7172 h60
  text "FR-4 High Tg" at 6818.4,7172 h60
  text "5.00mil" at 7678.16,7172 h60
  text "4.2" at 8328,7172 h60
  text "2" at 5468.74,7052 h60
  text "Signal Layer 1" at 5878.66,7052 h60
  text "2.80mil" at 7678.16,7052 h60
  text "Dielectric 2" at 5878.66,6932 h60
  text "FR-4 High Tg" at 6818.4,6932 h60
  text "40.00mil" at 7678.16,6932 h60
  text "4.2" at 8328,6932 h60
  text "3" at 5468.74,6812 h60
  text "Signal Layer 2" at 5878.66,6812 h60
  text "2.80mil" at 7678.16,6812 h60
  text "Dielectric 3" at 5878.66,6692 h60
  text "FR-4 High Tg" at 6818.4,6692 h60
  text "5.00mil" at 7678.16,6692 h60
  text "4.2" at 8328,6692 h60
  text "4" at 5468.74,6572 h60
  text "Bottom Layer" at 5878.66,6572 h60
  text "2.80mil" at 7678.16,6572 h60
  text "Bottom Solder" at 5878.66,6452 h60
  text "Solder Resist" at 6818.4,6452 h60
  text "0.40mil" at 7678.16,6452 h60
  text "3.5" at 8328,6452 h60
  text "Bottom Overlay" at 5878.66,6332 h60
  text "Total board thickness (Board Layer Stack):" at 5468.74,6212 h60
  text "62.00mil" at 7947.97,6212 h60
  text ".Layer_Name" at 577,-858.49 h60
M13 Component Bodies Top:
  text ".Layer_Name" at 577,-858.49 h60
M14 Component Bodies Bottom:
  text ".Layer_Name" at 577,-858.49 h60
M15 Courtyards Top:
  text ".Layer_Name" at 577,-858.49 h60
M16 Courtyards Bottom:
  text ".Layer_Name" at 577,-858.49 h60
Drill Drawing:
  circle w10: c2029.14,7959.6 r27.63
  lines w10: 2001.52,7186.06 2056.77,7186.06 2056.77,7241.31 2001.52,7241.31 2001.52,7186.06 ; 2001.52,7338 2029.14,7310.38 2056.77,7338 2029.14,7365.63 2001.52,7338 ; 2001.52,7448.51 2015.33,7448.51 2015.33,7434.7 2042.96,7434.7 2042.96,7448.51 2056.77,7448.51 2056.77,7476.14 2042.96,7476.14 2042.96,7489.95 2015.33,7489.95 2015.33,7476.14 2001.52,7476.14 2001.52,7448.51 ; 2001.52,7559.02 2001.52,7572.83 2015.33,7586.64 2001.52,7600.46 2001.52,7614.27 2015.33,7614.27 2029.14,7600.46 2042.96,7614.27 2056.77,7614.27 2056.77,7600.46 2042.96,7586.64 2056.77,7572.83 2056.77,7559.02 2042.96,7559.02 2029.14,7572.83 2015.33,7559.02 2001.52,7559.02 ; 2001.52,7683.34 2029.14,7697.15 2056.77,7683.34 2042.96,7710.96 2056.77,7738.59 2029.14,7724.78 2001.52,7738.59 2015.33,7710.96 2001.52,7683.34 ; 2001.52,7862.91 2056.77,7862.91 2029.14,7807.66 2001.52,7862.91
  lines w12: 1951.43,7148.76 5105.63,7148.76 ; 1951.43,8019 5105.63,8019 ; 2289.29,7024.44 2289.29,8143.32 ; 2590.65,7024.44 2590.65,8143.32 ; 3180.56,7024.44 3180.56,8143.32 ; 3439.7,7024.44 3439.7,8143.32 ; 3814.86,7024.44 3814.86,8143.32 ; 4539.19,7024.44 4539.19,8143.32 ; 1951.43,7024.44 5105.63,7024.44 5105.63,8143.32 1951.43,8143.32 1951.43,7024.44
  text "Symbol" at 2026.02,8056.3 h72
  text "Count" at 2326.59,8056.3 h72
  text "Hole Size" at 2627.95,8056.3 h72
  text "Plated" at 3217.86,8056.3 h72
  text "Hole Type" at 3477,8056.3 h72
  text "Drill Layer Pair" at 3852.16,8056.3 h72
  text "Hole Tolerance" at 4576.49,8056.3 h72
  text "208" at 2326.59,7931.98 h60
  text "7.87mil (0.200mm)" at 2627.95,7931.98 h60
  text "PTH" at 3217.86,7931.98 h60
  text "Round" at 3477,7931.98 h60
  text "Top Layer - Bottom Layer" at 3852.16,7931.98 h60
  text "437" at 2326.59,7807.66 h60
  text "8.00mil (0.203mm)" at 2627.95,7807.66 h60
  text "PTH" at 3217.86,7807.66 h60
  text "Round" at 3477,7807.66 h60
  text "Top Layer - Bottom Layer" at 3852.16,7807.66 h60
  text "32" at 2326.59,7683.34 h60
  text "8.00mil (0.203mm)" at 2627.95,7683.34 h60
  text "PTH" at 3217.86,7683.34 h60
  text "Round" at 3477,7683.34 h60
  text "Top Layer - Bottom Layer" at 3852.16,7683.34 h60
  text "8" at 2326.59,7559.02 h60
  text "39.37mil (1.000mm)" at 2627.95,7559.02 h60
  text "PTH" at 3217.86,7559.02 h60
  text "Round" at 3477,7559.02 h60
  text "Top Layer - Bottom Layer" at 3852.16,7559.02 h60
  text "6" at 2326.59,7434.7 h60
  text "40.00mil (1.016mm)" at 2627.95,7434.7 h60
  text "PTH" at 3217.86,7434.7 h60
  text "Round" at 3477,7434.7 h60
  text "Top Layer - Bottom Layer" at 3852.16,7434.7 h60
  text "4" at 2326.59,7310.38 h60
  text "51.18mil (1.300mm)" at 2627.95,7310.38 h60
  text "PTH" at 3217.86,7310.38 h60
  text "Round" at 3477,7310.38 h60
  text "Top Layer - Bottom Layer" at 3852.16,7310.38 h60
  text "4" at 2326.59,7186.06 h60
  text "125.98mil (3.200mm)" at 2627.95,7186.06 h60
  text "PTH" at 3217.86,7186.06 h60
  text "Round" at 3477,7186.06 h60
  text "Top Layer - Bottom Layer" at 3852.16,7186.06 h60
  text "699 Total" at 2326.59,7061.74 h60
  text ".Layer_Name" at 577,-858.49 h60
M17 Embedded Cavity:
  text ".Layer_Name" at 577,-858.49 h60
M18 Embedded Assembly:
  text ".Layer_Name" at 577,-858.49 h60
M19 Embedded Keepout:
  text ".Layer_Name" at 577,-858.49 h60

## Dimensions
0,0 to 4000,0 on M2 Board Dimensions
0,0 to 0,3000 on M2 Board Dimensions
0,-400 to 1000,-400 on M2 Board Dimensions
